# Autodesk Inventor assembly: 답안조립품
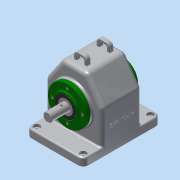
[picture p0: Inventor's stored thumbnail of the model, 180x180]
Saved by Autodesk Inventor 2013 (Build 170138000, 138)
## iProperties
Created: 2016-12
Part Number: 답안조립품
Document SubType Name: Assembly
Designer: Administrator
Author: Administrator
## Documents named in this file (12)
- C:\Users\Administrator\Desktop\461208V1012\답안조립품.iam
- C:\Users\Administrator\Desktop\461208V1012\1.본체.ipt
- C:\Users\Administrator\Desktop\461208V1012\뒤커버.ipt
- C:\Users\Administrator\Desktop\461208V1012\축.ipt
- C:\Users\Administrator\Desktop\461208V1012\베어링 6203.ipt
- C:\Users\Administrator\Desktop\461208V1012\키 - 6 x 6 x 22.ipt
- C:\Users\Administrator\Desktop\461208V1012\스퍼기어.ipt
- C:\Users\Administrator\Desktop\461208V1012\부시.ipt
- C:\Users\Administrator\Desktop\461208V1012\앞커버.ipt
- C:\Users\Administrator\Desktop\461208V1012\오일씰 28 40 8.ipt
- C:\Users\Administrator\Desktop\461208V1012\볼트 M3 x 10.ipt
- C:\Users\Administrator\Desktop\461208V1012\볼트 M3 x 8.ipt
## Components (9 placed, 3 different names)
1. 1.본체:1
2. ISO 4762 M3 x 10:1
3. ISO 4762 M3 x 10:2
4. ISO 4762 M3 x 10:3
5. ISO 4762 M3 x 10:4
6. ISO 4762 M3 x 8:1
7. ISO 4762 M3 x 8:2
8. ISO 4762 M3 x 8:3
9. ISO 4762 M3 x 8:4
